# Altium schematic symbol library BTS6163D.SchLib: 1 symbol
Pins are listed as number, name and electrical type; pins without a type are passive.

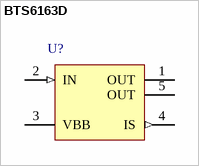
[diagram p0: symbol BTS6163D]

## BTS6163D
designator U?
PROFET Smart Highside Power Switch, 1 Channel, 6.5 A Load Current, -40 to 150 degC, PG-TO252-5-11, Reel, Green; Manufacturer: Infineon; PartNumber: BTS6163D; Channels: 1; Green: TRUE; Group: Automotive Qualified; Load Current (typ): 6.5 A; Ptot (max): 59 W; Recommended Operating Voltage Max.: 62 V; Recommended Operating Voltage Min.: 5.5 V; RON @ 25degreesC: 20 mOhm; RON(max) @ 150degreesC: 40 mOhm; toff (max): 500 us; ton (max): 300 us
footprint INF-PG-TO252-5-11_N (DPAK, 5-Leads, Body 6.5x6.12mm, Pitch 1.14mm, IPC Medium Density)
footprint INF-PG-TO252-5-11_L (DPAK, 5-Leads, Body 6.5x6.12mm, Pitch 1.14mm, IPC High Density)
footprint INF-PG-TO252-5-11_M (DPAK, 5-Leads, Body 6.5x6.12mm, Pitch 1.14mm, IPC Low Density)
pins: 1 OUT (hiz) "Output; output to the load; pin 1 and 5 must be externally shorted.", 2 IN (in) "Input; activates the power switch if shorted to ground.", 3 VBB (power) "Supply Voltage; positive power supply voltage; tab and pin 3 are internally shorted.", 4 IS (out) "Sense Output; Diagnostic feedback; provides at normal operation a sense current proportional to the load current; in case of overload, overtemperature and/or short circuit a defined current is provided.", 5 OUT (hiz) "Output; output to the load; pin 1 and 5 must be externally shorted."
